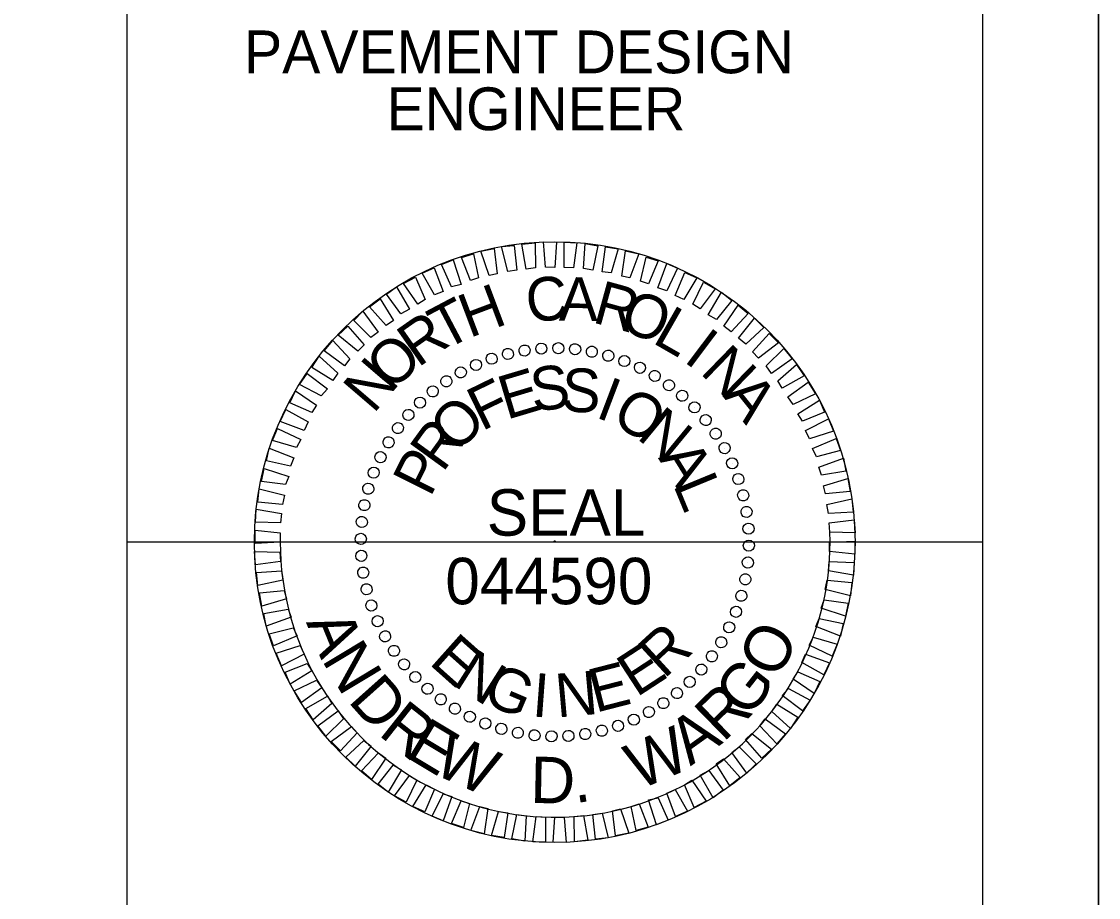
# Model space of a CAD drawing. Extents: x 1184121 to 1184397, y 1246506 to 1246661.
# Drawn here: x 1184342.61 to 1184360.32, y 1246609.59 to 1246623.99 of the extents above; entities that cross this region are included whole.
import ezdxf

# ---------------------------------------------------------------- set-up
doc = ezdxf.new("R2010")
doc.units = 0
for name, color, linetype in [('Scratch_Level_0', 7, 'Continuous'), ('Scratch_Level_3', 7, 'Continuous'), ('Sheet PE Seal Cell', 7, 'Continuous'), ('Sheet Plan CELL', 7, 'Continuous'), ('Sheet Plot Border Outside CELL', 7, 'Continuous'), ('z - Construction', 7, 'Continuous')]:
    doc.layers.add(name, color=color, linetype=linetype)

msp = doc.modelspace()

# ---------------------------------------------------------------- linework, layer by layer
at = {"layer": 'Scratch_Level_0'}
msp.add_arc((1184351.386, 1246615.431), 4.523, 180.0118, 2.0847, dxfattribs=at)
at = {"layer": 'Scratch_Level_3'}
msp.add_line((1184358.424, 1246615.433), (1184344.334, 1246615.433), dxfattribs=at)
msp.add_circle((1184351.379, 1246615.433), 4.94, dxfattribs=at)
at = {"layer": 'Sheet PE Seal Cell'}
for p, q in [((1184351.158, 1246618.619), (1184351.158, 1246618.619)), ((1184351.439, 1246618.625), (1184351.439, 1246618.625)), ((1184350.337, 1246618.454), (1184350.337, 1246618.454)), ((1184350.605, 1246618.53), (1184350.605, 1246618.53)), ((1184350.885, 1246618.581), (1184350.885, 1246618.581)), ((1184351.719, 1246618.606), (1184351.719, 1246618.606)), ((1184351.992, 1246618.562), (1184351.992, 1246618.562)), ((1184352.26, 1246618.505), (1184352.26, 1246618.505)), ((1184350.083, 1246618.352), (1184350.083, 1246618.352)), ((1184352.527, 1246618.415), (1184352.527, 1246618.415)), ((1184352.781, 1246618.301), (1184352.781, 1246618.301)), ((1184349.835, 1246618.224), (1184349.835, 1246618.224)), ((1184353.03, 1246618.174), (1184353.03, 1246618.174)), ((1184349.37, 1246617.919), (1184349.37, 1246617.919)), ((1184349.593, 1246618.078), (1184349.593, 1246618.078)), ((1184353.259, 1246618.014), (1184353.259, 1246618.014)), ((1184349.16, 1246617.728), (1184349.16, 1246617.728)), ((1184353.481, 1246617.843), (1184353.481, 1246617.843)), ((1184353.679, 1246617.652), (1184353.679, 1246617.652)), ((1184348.969, 1246617.531), (1184348.969, 1246617.531)), ((1184353.87, 1246617.442), (1184353.87, 1246617.442)), ((1184348.797, 1246617.308), (1184348.797, 1246617.308)), ((1184354.029, 1246617.219), (1184354.029, 1246617.219)), ((1184348.638, 1246617.079), (1184348.638, 1246617.079)), ((1184354.175, 1246616.977), (1184354.175, 1246616.977)), ((1184348.511, 1246616.831), (1184348.511, 1246616.831)), ((1184354.302, 1246616.729), (1184354.302, 1246616.729)), ((1184348.396, 1246616.576), (1184348.396, 1246616.576)), ((1184354.404, 1246616.474), (1184354.404, 1246616.474)), ((1184348.307, 1246616.309), (1184348.307, 1246616.309)), ((1184354.481, 1246616.207), (1184354.481, 1246616.207)), ((1184348.25, 1246616.042), (1184348.25, 1246616.042)), ((1184354.532, 1246615.927), (1184354.532, 1246615.927)), ((1184348.205, 1246615.768), (1184348.205, 1246615.768)), ((1184354.57, 1246615.653), (1184354.57, 1246615.653)), ((1184348.186, 1246615.488), (1184348.186, 1246615.488)), ((1184351.381, 1246615.431), (1184351.381, 1246615.431)), ((1184354.576, 1246615.373), (1184354.576, 1246615.373)), ((1184348.193, 1246615.208), (1184348.193, 1246615.208)), ((1184354.557, 1246615.093), (1184354.557, 1246615.093)), ((1184348.231, 1246614.934), (1184348.231, 1246614.934)), ((1184354.512, 1246614.82), (1184354.512, 1246614.82)), ((1184348.282, 1246614.654), (1184348.282, 1246614.654)), ((1184354.455, 1246614.552), (1184354.455, 1246614.552)), ((1184348.358, 1246614.387), (1184348.358, 1246614.387)), ((1184354.366, 1246614.285), (1184354.366, 1246614.285)), ((1184348.46, 1246614.132), (1184348.46, 1246614.132)), ((1184354.252, 1246614.03), (1184354.252, 1246614.03)), ((1184348.587, 1246613.884), (1184348.587, 1246613.884)), ((1184354.124, 1246613.782), (1184354.124, 1246613.782)), ((1184348.734, 1246613.642), (1184348.734, 1246613.642)), ((1184353.965, 1246613.553), (1184353.965, 1246613.553)), ((1184348.893, 1246613.419), (1184348.893, 1246613.419)), ((1184353.793, 1246613.33), (1184353.793, 1246613.33)), ((1184349.084, 1246613.209), (1184349.084, 1246613.209)), ((1184353.602, 1246613.133), (1184353.602, 1246613.133)), ((1184349.281, 1246613.018), (1184349.281, 1246613.018)), ((1184349.504, 1246612.847), (1184349.504, 1246612.847)), ((1184353.17, 1246612.783), (1184353.17, 1246612.783)), ((1184353.392, 1246612.942), (1184353.392, 1246612.942)), ((1184349.733, 1246612.688), (1184349.733, 1246612.688)), ((1184352.928, 1246612.637), (1184352.928, 1246612.637)), ((1184349.981, 1246612.56), (1184349.981, 1246612.56)), ((1184350.236, 1246612.446), (1184350.236, 1246612.446)), ((1184352.68, 1246612.509), (1184352.68, 1246612.509)), ((1184350.503, 1246612.357), (1184350.503, 1246612.357)), ((1184350.77, 1246612.299), (1184350.77, 1246612.299)), ((1184351.044, 1246612.255), (1184351.044, 1246612.255)), ((1184351.604, 1246612.242), (1184351.604, 1246612.242)), ((1184351.878, 1246612.28), (1184351.878, 1246612.28)), ((1184352.158, 1246612.331), (1184352.158, 1246612.331)), ((1184352.425, 1246612.407), (1184352.425, 1246612.407)), ((1184351.324, 1246612.236), (1184351.324, 1246612.236))]:
    msp.add_line(p, q, dxfattribs=at)
for points in [[(1184350.299, 1246619.816), (1184350.166, 1246620.217), (1184350.382, 1246620.261), (1184350.433, 1246619.847)], [(1184350.605, 1246619.886), (1184350.503, 1246620.293), (1184350.713, 1246620.312), (1184350.758, 1246619.905)], [(1184350.91, 1246619.924), (1184350.84, 1246620.331), (1184351.057, 1246620.357), (1184351.063, 1246619.943)], [(1184351.228, 1246619.956), (1184351.197, 1246620.369), (1184351.407, 1246620.363), (1184351.381, 1246619.949)], [(1184351.534, 1246619.949), (1184351.534, 1246620.363), (1184351.744, 1246620.357), (1184351.687, 1246619.943)], [(1184351.852, 1246619.93), (1184351.878, 1246620.344), (1184352.088, 1246620.306), (1184352.005, 1246619.905)], [(1184352.158, 1246619.879), (1184352.215, 1246620.287), (1184352.425, 1246620.255), (1184352.31, 1246619.86)], [(1184352.482, 1246619.809), (1184352.546, 1246620.223), (1184352.762, 1246620.172), (1184352.616, 1246619.777)], [(1184349.682, 1246619.631), (1184349.516, 1246620), (1184349.707, 1246620.077), (1184349.841, 1246619.669)], [(1184349.994, 1246619.733), (1184349.847, 1246620.115), (1184350.045, 1246620.172), (1184350.127, 1246619.777)], [(1184352.788, 1246619.726), (1184352.883, 1246620.121), (1184353.081, 1246620.057), (1184352.921, 1246619.682)], [(1184349.402, 1246619.497), (1184349.198, 1246619.854), (1184349.396, 1246619.943), (1184349.542, 1246619.555)], [(1184353.074, 1246619.612), (1184353.221, 1246620.013), (1184353.399, 1246619.936), (1184353.221, 1246619.567)], [(1184353.361, 1246619.491), (1184353.52, 1246619.866), (1184353.717, 1246619.777), (1184353.501, 1246619.421)], [(1184349.128, 1246619.345), (1184348.893, 1246619.688), (1184349.09, 1246619.79), (1184349.249, 1246619.421)], [(1184353.653, 1246619.345), (1184353.825, 1246619.707), (1184354.016, 1246619.599), (1184353.774, 1246619.268)], [(1184348.848, 1246619.186), (1184348.613, 1246619.51), (1184348.778, 1246619.631), (1184348.988, 1246619.262)], [(1184353.902, 1246619.173), (1184354.124, 1246619.542), (1184354.29, 1246619.408), (1184354.042, 1246619.096)], [(1184348.606, 1246618.995), (1184348.333, 1246619.3), (1184348.505, 1246619.434), (1184348.727, 1246619.077)], [(1184354.162, 1246618.982), (1184354.398, 1246619.332), (1184354.563, 1246619.192), (1184354.283, 1246618.893)], [(1184348.352, 1246618.797), (1184348.072, 1246619.077), (1184348.225, 1246619.23), (1184348.473, 1246618.886)], [(1184348.142, 1246618.575), (1184347.817, 1246618.835), (1184347.976, 1246618.982), (1184348.244, 1246618.676)], [(1184354.404, 1246618.785), (1184354.665, 1246619.115), (1184354.818, 1246618.963), (1184354.525, 1246618.689)], [(1184354.633, 1246618.562), (1184354.907, 1246618.861), (1184355.06, 1246618.708), (1184354.729, 1246618.46)], [(1184347.919, 1246618.333), (1184347.588, 1246618.581), (1184347.728, 1246618.746), (1184348.008, 1246618.447)], [(1184354.856, 1246618.333), (1184355.149, 1246618.619), (1184355.283, 1246618.447), (1184354.945, 1246618.205)], [(1184347.728, 1246618.091), (1184347.384, 1246618.307), (1184347.505, 1246618.492), (1184347.811, 1246618.212)], [(1184355.047, 1246618.084), (1184355.359, 1246618.352), (1184355.48, 1246618.167), (1184355.123, 1246617.964)], [(1184347.537, 1246617.836), (1184347.181, 1246618.027), (1184347.308, 1246618.205), (1184347.639, 1246617.951)], [(1184347.384, 1246617.563), (1184347.022, 1246617.722), (1184347.117, 1246617.919), (1184347.461, 1246617.684)], [(1184355.213, 1246617.824), (1184355.55, 1246618.065), (1184355.671, 1246617.874), (1184355.302, 1246617.696)], [(1184355.378, 1246617.544), (1184355.734, 1246617.766), (1184355.817, 1246617.569), (1184355.454, 1246617.423)], [(1184347.257, 1246617.27), (1184346.863, 1246617.416), (1184346.958, 1246617.614), (1184347.321, 1246617.41)], [(1184355.505, 1246617.27), (1184355.881, 1246617.461), (1184355.964, 1246617.257), (1184355.569, 1246617.13)], [(1184347.13, 1246616.99), (1184346.735, 1246617.104), (1184346.818, 1246617.302), (1184347.2, 1246617.123)], [(1184355.62, 1246616.971), (1184356.008, 1246617.136), (1184356.078, 1246616.939), (1184355.684, 1246616.837)], [(1184347.034, 1246616.684), (1184346.64, 1246616.767), (1184346.684, 1246616.977), (1184347.085, 1246616.818)], [(1184355.722, 1246616.665), (1184356.129, 1246616.812), (1184356.167, 1246616.602), (1184355.766, 1246616.532)], [(1184346.952, 1246616.379), (1184346.557, 1246616.43), (1184346.602, 1246616.646), (1184347.003, 1246616.512)], [(1184355.798, 1246616.36), (1184356.199, 1246616.481), (1184356.237, 1246616.264), (1184355.836, 1246616.226)], [(1184346.901, 1246616.054), (1184346.493, 1246616.092), (1184346.519, 1246616.309), (1184346.933, 1246616.207)], [(1184355.855, 1246616.054), (1184356.269, 1246616.143), (1184356.288, 1246615.927), (1184355.881, 1246615.902)], [(1184346.869, 1246615.749), (1184346.455, 1246615.761), (1184346.468, 1246615.972), (1184346.882, 1246615.902)], [(1184355.894, 1246615.749), (1184356.307, 1246615.8), (1184356.32, 1246615.583), (1184355.906, 1246615.596)], [(1184346.863, 1246615.431), (1184346.449, 1246615.411), (1184346.449, 1246615.628), (1184346.863, 1246615.583)], [(1184355.9, 1246615.431), (1184356.314, 1246615.45), (1184356.314, 1246615.233), (1184355.9, 1246615.278)], [(1184346.869, 1246615.112), (1184346.455, 1246615.061), (1184346.443, 1246615.278), (1184346.856, 1246615.265)], [(1184355.894, 1246615.112), (1184356.307, 1246615.1), (1184356.295, 1246614.89), (1184355.881, 1246614.96)], [(1184346.907, 1246614.807), (1184346.493, 1246614.718), (1184346.474, 1246614.934), (1184346.882, 1246614.96)], [(1184355.862, 1246614.807), (1184356.269, 1246614.769), (1184356.244, 1246614.552), (1184355.83, 1246614.654)], [(1184346.964, 1246614.501), (1184346.563, 1246614.38), (1184346.525, 1246614.597), (1184346.926, 1246614.635)], [(1184355.811, 1246614.482), (1184356.205, 1246614.431), (1184356.161, 1246614.215), (1184355.76, 1246614.349)], [(1184347.041, 1246614.196), (1184346.633, 1246614.049), (1184346.595, 1246614.26), (1184346.996, 1246614.33)], [(1184347.143, 1246613.89), (1184346.754, 1246613.725), (1184346.684, 1246613.922), (1184347.079, 1246614.024)], [(1184355.728, 1246614.177), (1184356.123, 1246614.094), (1184356.078, 1246613.884), (1184355.677, 1246614.043)], [(1184355.633, 1246613.871), (1184356.027, 1246613.757), (1184355.944, 1246613.559), (1184355.563, 1246613.738)], [(1184347.257, 1246613.591), (1184346.882, 1246613.4), (1184346.799, 1246613.604), (1184347.193, 1246613.731)], [(1184355.505, 1246613.591), (1184355.9, 1246613.445), (1184355.804, 1246613.248), (1184355.442, 1246613.451)], [(1184347.384, 1246613.318), (1184347.028, 1246613.095), (1184346.945, 1246613.292), (1184347.308, 1246613.439)], [(1184347.55, 1246613.038), (1184347.213, 1246612.796), (1184347.092, 1246612.987), (1184347.461, 1246613.165)], [(1184355.378, 1246613.298), (1184355.741, 1246613.139), (1184355.645, 1246612.942), (1184355.302, 1246613.178)], [(1184355.225, 1246613.025), (1184355.582, 1246612.834), (1184355.454, 1246612.656), (1184355.123, 1246612.91)], [(1184347.715, 1246612.777), (1184347.404, 1246612.509), (1184347.283, 1246612.694), (1184347.639, 1246612.898)], [(1184355.034, 1246612.77), (1184355.378, 1246612.554), (1184355.257, 1246612.369), (1184354.952, 1246612.649)], [(1184347.906, 1246612.528), (1184347.614, 1246612.242), (1184347.48, 1246612.414), (1184347.817, 1246612.656)], [(1184354.843, 1246612.528), (1184355.174, 1246612.28), (1184355.034, 1246612.115), (1184354.754, 1246612.414)], [(1184348.129, 1246612.299), (1184347.855, 1246612), (1184347.703, 1246612.153), (1184348.034, 1246612.401)], [(1184354.621, 1246612.287), (1184354.945, 1246612.026), (1184354.786, 1246611.879), (1184354.519, 1246612.185)], [(1184348.358, 1246612.077), (1184348.097, 1246611.746), (1184347.944, 1246611.898), (1184348.237, 1246612.172)], [(1184354.411, 1246612.064), (1184354.691, 1246611.784), (1184354.538, 1246611.631), (1184354.29, 1246611.975)], [(1184348.6, 1246611.879), (1184348.365, 1246611.529), (1184348.199, 1246611.669), (1184348.479, 1246611.968)], [(1184348.861, 1246611.688), (1184348.638, 1246611.319), (1184348.473, 1246611.453), (1184348.721, 1246611.765)], [(1184354.156, 1246611.867), (1184354.43, 1246611.561), (1184354.258, 1246611.427), (1184354.035, 1246611.784)], [(1184349.109, 1246611.516), (1184348.937, 1246611.154), (1184348.746, 1246611.262), (1184348.988, 1246611.593)], [(1184353.914, 1246611.676), (1184354.15, 1246611.351), (1184353.984, 1246611.23), (1184353.774, 1246611.599)], [(1184349.402, 1246611.37), (1184349.243, 1246610.995), (1184349.046, 1246611.084), (1184349.262, 1246611.44)], [(1184353.361, 1246611.364), (1184353.564, 1246611.007), (1184353.367, 1246610.918), (1184353.221, 1246611.306)], [(1184353.634, 1246611.516), (1184353.87, 1246611.173), (1184353.672, 1246611.071), (1184353.513, 1246611.44)], [(1184349.688, 1246611.249), (1184349.542, 1246610.848), (1184349.364, 1246610.925), (1184349.542, 1246611.294)], [(1184349.975, 1246611.135), (1184349.879, 1246610.74), (1184349.682, 1246610.804), (1184349.841, 1246611.179)], [(1184353.081, 1246611.23), (1184353.246, 1246610.861), (1184353.055, 1246610.785), (1184352.921, 1246611.192)], [(1184350.28, 1246611.052), (1184350.217, 1246610.638), (1184350, 1246610.689), (1184350.147, 1246611.084)], [(1184350.605, 1246610.982), (1184350.548, 1246610.575), (1184350.337, 1246610.606), (1184350.452, 1246611.001)], [(1184352.463, 1246611.046), (1184352.597, 1246610.645), (1184352.38, 1246610.6), (1184352.33, 1246611.014)], [(1184352.769, 1246611.128), (1184352.915, 1246610.746), (1184352.718, 1246610.689), (1184352.635, 1246611.084)], [(1184350.91, 1246610.931), (1184350.885, 1246610.517), (1184350.675, 1246610.555), (1184350.758, 1246610.956)], [(1184351.228, 1246610.912), (1184351.228, 1246610.498), (1184351.018, 1246610.505), (1184351.076, 1246610.918)], [(1184351.534, 1246610.906), (1184351.566, 1246610.492), (1184351.356, 1246610.498), (1184351.381, 1246610.912)], [(1184351.852, 1246610.937), (1184351.922, 1246610.53), (1184351.706, 1246610.505), (1184351.699, 1246610.918)], [(1184352.158, 1246610.976), (1184352.26, 1246610.568), (1184352.049, 1246610.549), (1184352.005, 1246610.956)]]:
    msp.add_lwpolyline(points, close=True, dxfattribs=at)
for centre, major_axis in [((1184350.609, 1246618.528), (-0.0222, 0.0889)), ((1184350.882, 1246618.584), (-0.0143, 0.0905)), ((1184351.159, 1246618.615), (-0.0064, 0.0914)), ((1184351.437, 1246618.622), (0.0016, 0.0916)), ((1184351.715, 1246618.605), (0.0096, 0.0911)), ((1184351.99, 1246618.564), (0.0175, 0.09)), ((1184350.083, 1246618.347), (-0.0373, 0.0837)), ((1184350.342, 1246618.449), (-0.0298, 0.0867)), ((1184352.261, 1246618.499), (0.0253, 0.0881)), ((1184352.525, 1246618.411), (0.0328, 0.0856)), ((1184349.834, 1246618.223), (-0.0444, 0.0802)), ((1184352.781, 1246618.3), (0.0402, 0.0824)), ((1184353.025, 1246618.167), (0.0472, 0.0786)), ((1184349.596, 1246618.077), (-0.0512, 0.076)), ((1184353.258, 1246618.013), (0.0539, 0.0741)), ((1184349.372, 1246617.911), (-0.0577, 0.0712)), ((1184353.476, 1246617.84), (0.0601, 0.0692)), ((1184349.164, 1246617.727), (-0.0637, 0.0659)), ((1184353.678, 1246617.648), (0.0659, 0.0637)), ((1184348.972, 1246617.525), (-0.0692, 0.0601)), ((1184348.799, 1246617.307), (-0.0741, 0.0539)), ((1184353.862, 1246617.44), (0.0712, 0.0577)), ((1184354.028, 1246617.216), (0.076, 0.0512)), ((1184348.645, 1246617.075), (-0.0786, 0.0472)), ((1184354.173, 1246616.978), (0.0802, 0.0444)), ((1184348.512, 1246616.83), (-0.0824, 0.0402)), ((1184348.401, 1246616.575), (-0.0856, 0.0328)), ((1184354.298, 1246616.729), (0.0837, 0.0373)), ((1184354.4, 1246616.47), (0.0867, 0.0298)), ((1184348.313, 1246616.31), (-0.0881, 0.0253)), ((1184348.248, 1246616.04), (-0.09, 0.0175)), ((1184354.479, 1246616.203), (0.0889, 0.0222)), ((1184354.534, 1246615.93), (0.0905, 0.0143)), ((1184348.206, 1246615.764), (-0.0911, 0.0096)), ((1184354.566, 1246615.653), (0.0914, 0.0064)), ((1184348.189, 1246615.486), (-0.0916, 0.0016)), ((1184354.573, 1246615.375), (0.0916, -0.0016)), ((1184348.197, 1246615.208), (-0.0914, -0.0064)), ((1184354.556, 1246615.097), (0.0911, -0.0096)), ((1184348.228, 1246614.931), (-0.0905, -0.0143)), ((1184354.515, 1246614.821), (0.09, -0.0175)), ((1184348.284, 1246614.658), (-0.0889, -0.0222)), ((1184354.45, 1246614.551), (0.0881, -0.0253)), ((1184348.363, 1246614.391), (-0.0867, -0.0298)), ((1184354.362, 1246614.287), (0.0856, -0.0328)), ((1184348.465, 1246614.132), (-0.0837, -0.0373)), ((1184354.25, 1246614.031), (0.0824, -0.0402)), ((1184348.589, 1246613.883), (-0.0802, -0.0444)), ((1184354.118, 1246613.786), (0.0786, -0.0472)), ((1184348.735, 1246613.645), (-0.076, -0.0512)), ((1184353.964, 1246613.554), (0.0741, -0.0539)), ((1184348.9, 1246613.422), (-0.0712, -0.0577)), ((1184349.085, 1246613.213), (-0.0659, -0.0637)), ((1184353.791, 1246613.336), (0.0692, -0.0601)), ((1184349.287, 1246613.021), (-0.0601, -0.0692)), ((1184353.599, 1246613.134), (0.0637, -0.0659)), ((1184349.505, 1246612.848), (-0.0539, -0.0741)), ((1184353.39, 1246612.95), (0.0577, -0.0712)), ((1184349.737, 1246612.694), (-0.0472, -0.0786)), ((1184353.166, 1246612.784), (0.0512, -0.076)), ((1184349.982, 1246612.561), (-0.0402, -0.0824)), ((1184352.68, 1246612.514), (0.0373, -0.0837)), ((1184352.929, 1246612.638), (0.0444, -0.0802)), ((1184350.237, 1246612.45), (-0.0328, -0.0856)), ((1184350.501, 1246612.362), (-0.0253, -0.0881)), ((1184352.154, 1246612.333), (0.0222, -0.0889)), ((1184352.421, 1246612.412), (0.0298, -0.0867)), ((1184350.772, 1246612.297), (-0.0175, -0.09)), ((1184351.048, 1246612.256), (-0.0096, -0.0911)), ((1184351.326, 1246612.239), (-0.0016, -0.0916)), ((1184351.604, 1246612.246), (0.0064, -0.0914)), ((1184351.881, 1246612.277), (0.0143, -0.0905))]:
    msp.add_ellipse(centre, major_axis=major_axis, ratio=0.999708, dxfattribs=at)
at = {"layer": 'Sheet Plan CELL'}
for p, q in [((1184344.345, 1246508.875), (1184344.348, 1246657.364)), ((1184358.419, 1246508.875), (1184358.423, 1246657.364))]:
    msp.add_line(p, q, dxfattribs=at)
msp.add_circle((1184351.379, 1246615.444), 0.012, dxfattribs=at)
at = {"layer": 'Sheet Plot Border Outside CELL'}
msp.add_lwpolyline([(1184121.05, 1246660.53), (1184360.324, 1246660.53), (1184360.324, 1246505.708), (1184121.05, 1246505.708)], close=True, dxfattribs=at)
at = {"layer": 'z - Construction'}
msp.add_line((1184360.324, 1246505.708), (1184360.324, 1246660.53), dxfattribs=at)

# ---------------------------------------------------------------- texts
at = {"layer": 'Sheet PE Seal Cell'}
for s, height, rotation, p in [('C', 0.718, 6.2199, (1184350.942, 1246619.039)), ('A', 0.718, 359.0203, (1184351.445, 1246619.077)), ('R', 0.718, 344.6211, (1184351.979, 1246619.052)), ('H', 0.718, 20.6195, (1184349.975, 1246618.785)), ('O', 0.718, 337.4212, (1184352.406, 1246618.956)), ('T', 0.718, 27.8198, (1184349.561, 1246618.575)), ('R', 0.718, 35.0205, (1184349.128, 1246618.294)), ('L', 0.718, 330.2209, (1184352.966, 1246618.721)), ('O', 0.718, 42.2217, (1184348.689, 1246617.9)), ('I', 0.718, 323.0201, (1184353.481, 1246618.415)), ('N', 0.718, 315.8189, (1184353.755, 1246618.218)), ('N', 0.718, 49.4235, (1184348.396, 1246617.531)), ('E', 0.718, 16.6111, (1184350.586, 1246617.442)), ('S', 0.718, 7.2556, (1184351.025, 1246617.575)), ('S', 0.718, 357.9004, (1184351.483, 1246617.582)), ('F', 0.718, 25.967, (1184350.178, 1246617.251)), ('I', 0.718, 339.1896, (1184352.03, 1246617.493)), ('O', 0.718, 329.8335, (1184352.285, 1246617.403)), ('A', 0.718, 308.6172, (1184354.131, 1246617.843)), ('O', 0.718, 44.6812, (1184349.758, 1246616.875)), ('N', 0.718, 320.4766, (1184352.711, 1246617.149)), ('R', 0.718, 54.0397, (1184349.536, 1246616.563)), ('P', 0.718, 63.3989, (1184349.332, 1246616.156)), ('A', 0.718, 301.7603, (1184353.074, 1246616.818)), ('L', 0.718, 292.4009, (1184353.322, 1246616.379)), ('SEAL', 0.7635, 360, (1184350.261, 1246615.539)), ('A', 0.763, 292.2016, (1184347.285, 1246614.115)), ('R', 0.718, 42.4814, (1184353.176, 1246613.171)), ('O', 0.763, 62.5158, (1184355.043, 1246613.156)), ('E', 0.718, 318.2769, (1184349.294, 1246613.439)), ('N', 0.763, 301.0323, (1184347.536, 1246613.501)), ('N', 0.718, 327.634, (1184349.676, 1246613.095)), ('E', 0.718, 33.1241, (1184352.724, 1246612.872)), ('G', 0.718, 336.9902, (1184350.159, 1246612.808)), ('N', 0.718, 5.0564, (1184351.419, 1246612.547)), ('E', 0.718, 14.4118, (1184352.049, 1246612.624)), ('G', 0.763, 51.8017, (1184354.556, 1246612.516)), ('D', 0.763, 311.7464, (1184347.962, 1246612.819)), ('I', 0.718, 355.7012, (1184350.993, 1246612.567)), ('R', 0.763, 44.3296, (1184354.15, 1246612.128)), ('R', 0.763, 321.6115, (1184348.46, 1246612.271)), ('A', 0.763, 35.4989, (1184353.61, 1246611.743)), ('E', 0.763, 329.0836, (1184348.896, 1246611.917)), ('W', 0.763, 22.9785, (1184352.758, 1246611.349)), ('W', 0.763, 336.1852, (1184349.349, 1246611.636)), ('D', 0.763, 358.8948, (1184350.972, 1246611.144)), ('.', 0.763, 8.7599, (1184351.713, 1246611.137))]:
    msp.add_text(s, height=height, rotation=rotation, dxfattribs=at).set_placement(p)
msp.add_text('044590', height=0.7635, dxfattribs=at).set_placement((1184349.579, 1246614.411))
at = {"layer": 'Sheet Plan CELL'}
for s, height, p in [('PAVEMENT DESIGN', 0.70377, (1184346.268, 1246623.143)), ('ENGINEER', 0.7038, (1184348.612, 1246622.207))]:
    msp.add_text(s, height=height, rotation=0, dxfattribs=at).set_placement(p)

doc.saveas('drawing.dxf')
